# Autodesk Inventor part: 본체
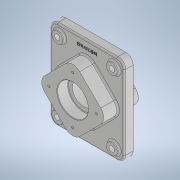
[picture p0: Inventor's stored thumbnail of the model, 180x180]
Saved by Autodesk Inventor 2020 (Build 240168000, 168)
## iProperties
Created: 2021-07
Part Number: 본체
Material: 일반
Document SubType Name: Modeling
Designer: Owner
Density: 1 g/cm^3
Appearance: 기본값
Mass: 807.976 g
Surface Area: 961.758 cm^2
Volume: 807.976 cm^3
Author: Owner
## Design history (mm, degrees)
sketch "스케치1"
  geometry: L1 (-75, 90)-(75, 90); L2 (75, 90)-(75, -90); L3 (75, -90)-(-75, -90); L4 (-75, -90)-(-75, 90); L5 (-75, 90)-(75, -90); L6 (75, 90)-(-75, -90); 1 further point
  constraints: 12 end point, 2 midpoint, 2 parallel, 1 horizontal, 1 perpendicular
  dimensions: "d0" = 150 distance of L2.end L3.end; "d1" = 180 distance of L1.end L2.end
extrude "돌출1" new body sketch "스케치1" stored distance "d2" = 18; taper "d3" = 0 deg
sketch "스케치2"
  geometry: L1 (0, -70.711)-(70.711, 0); L2 (70.711, 0)-(0, 70.711); L3 (0, 70.711)-(-70.711, 0); L4 (-70.711, 0)-(0, -70.711); L5 (0, -70.711)-(0, 70.711); L6 (70.711, 0)-(-70.711, 0); 3 further points
  constraints: 12 end point, 3 midpoint, 2 parallel, 1 coincident, 1 perpendicular, 1 vertical alignment
  dimensions: "d4" = 100 distance of L1.start L1.end; "d5" = 100 distance of L2.end L1.end
extrude "돌출2" join sketch "스케치2" distance "d6" = 23; taper "d7" = 0 deg
sketch "스케치3"
  geometry: L1 (-70.711, 0)-(0, -70.711) reference; L2 (0, -70.711)-(70.711, 0) reference; L3 (70.711, 0)-(0, 70.711) reference; L4 (75, -90)-(75, 90) reference; L5 (75, 90)-(-75, 90) reference; L6 (-75, 90)-(-75, -90) reference; L7 (-75, -90)-(75, -90) reference; L8 (0, 70.711)-(-70.711, 0) reference; 1 further point
extrude "돌출3" join sketch "스케치3" distance "d8" = 29; taper "d9" = 0 deg
sketch "스케치4"
  geometry: C1 r 31 at (0, 0); 1 further point
  constraints: 1 centre point, 1 coincident
  dimensions: "d10" = 62 diameter of C1
extrude "돌출4" cut sketch "스케치4" distance "d11" = 22; taper "d12" = 0 deg
sketch "스케치5"
  geometry: C1 r 31 at (0, 0); 1 further point
  constraints: 1 centre point, 1 coincident
  dimensions: "d13" = 62 diameter of C1
extrude "돌출5" cut sketch "스케치5" distance "d14" = 22; taper "d15" = 0 deg
sketch "스케치6"
  geometry: C1 r 22.5 at (0, 0); 1 further point
  constraints: 1 centre point, 1 coincident
  dimensions: "d16" = 45 diameter of C1
extrude "돌출6" cut sketch "스케치6" extent not by distance; stored distance "d17" = 22; taper "d18" = 0 deg
fillet "모깎기1" dims "d19" = 15
fillet "모깎기2" dims "d20" = 20
sketch "스케치7"
  geometry: L1 (-60, -90)-(60, -90) reference; C1 r 11 at (55, -70); 1 further point
  constraints: 1 centre point
  dimensions: "d21" = 22 diameter of C1; "d22" = 20 distance from line of C1.centre L1; "d23" = 55 horizontal distance of C1.centre point (0, 0)
extrude "돌출7" join sketch "스케치7" distance "d24" = 5; taper "d25" = 0 deg
sketch "스케치8"
  geometry: C1 r 11 at (0, 0) reference; 2 further points
  constraints: 1 coincident
hole "구멍1" sketch "스케치8" at (0, 0) diameter "d26" = 11; stored, may be unused: countersink angle "d30" = 90 deg, drill point angle "d32" = 118 deg; dims "d27" = 8, "d28" = 4, "d29" = 2, "d31" = 11
sketch "스케치9" dims "d33" = 96
  geometry: L1 (0, 0)-(0, -48); C1 r 31 at (0, 0) reference; 2 further points
  constraints: 2 end point, 1 coincident, 1 vertical, 1 vertical alignment, 2 other
hole "구멍2" sketch "스케치9" at (0, -48) diameter "d34" = 4.917; stored, may be unused: countersink angle "d38" = 90 deg, drill point angle "d40" = 118 deg; dims "d35" = 10, "d36" = 4, "d37" = 2, "d39" = 13
sketch "스케치10"
  geometry: L1 (0, 0)-(0, 48); C1 r 22.5 at (0, 0) reference; C2 r 48 at (0, 0); C3 r 2.458 at (0, 48) reference; 1 further point
  constraints: 2 end point, 1 centre point, 1 coincident, 1 vertical
  dimensions: "d44" = 96 diameter of C2
hole "구멍3" sketch "스케치10" at (0, 48) diameter "d45" = 4.917; stored, may be unused: countersink angle "d49" = 90 deg, drill point angle "d51" = 118 deg; dims "d46" = 10, "d47" = 4, "d48" = 2, "d50" = 13
sketch "스케치11"
  geometry: L1 (-60, -90)-(60, -90) reference; 2 further points
  constraints: 1 vertical alignment, 1 other
  dimensions: "d55" = 15 distance from line of L1 point (0, -75)
feature "엠보싱1" sketch "스케치11" dims "d0" = 150, "d1" = 180, "d56" = 0.5, "d57" = 0
chamfer "모따기1" distance "d58" = 1; stored, may be unused: second distance "d59" = 2, angle "d60" = 45 deg
fillet "모깎기3" dims "d61" = 1
fillet "모깎기4" dims "d62" = 3
fillet "모깎기5" dims "d63" = 3
node "솔리드1"
mirror "미러1"
mirror "미러2"
pattern_circular "원형 패턴1" dims angle "d42" = 360 deg
pattern_circular "원형 패턴2" dims angle "d53" = 360 deg
node "투영된 루프1"
feature "A9D066F2-1C7D-4E18-AEED-F7BC21143FA4" dims "d26" = 11, "d27" = 8, "d28" = 4, "d29" = 2, "d30" = 90 deg, "d31" = 11, "d32" = 118 deg
